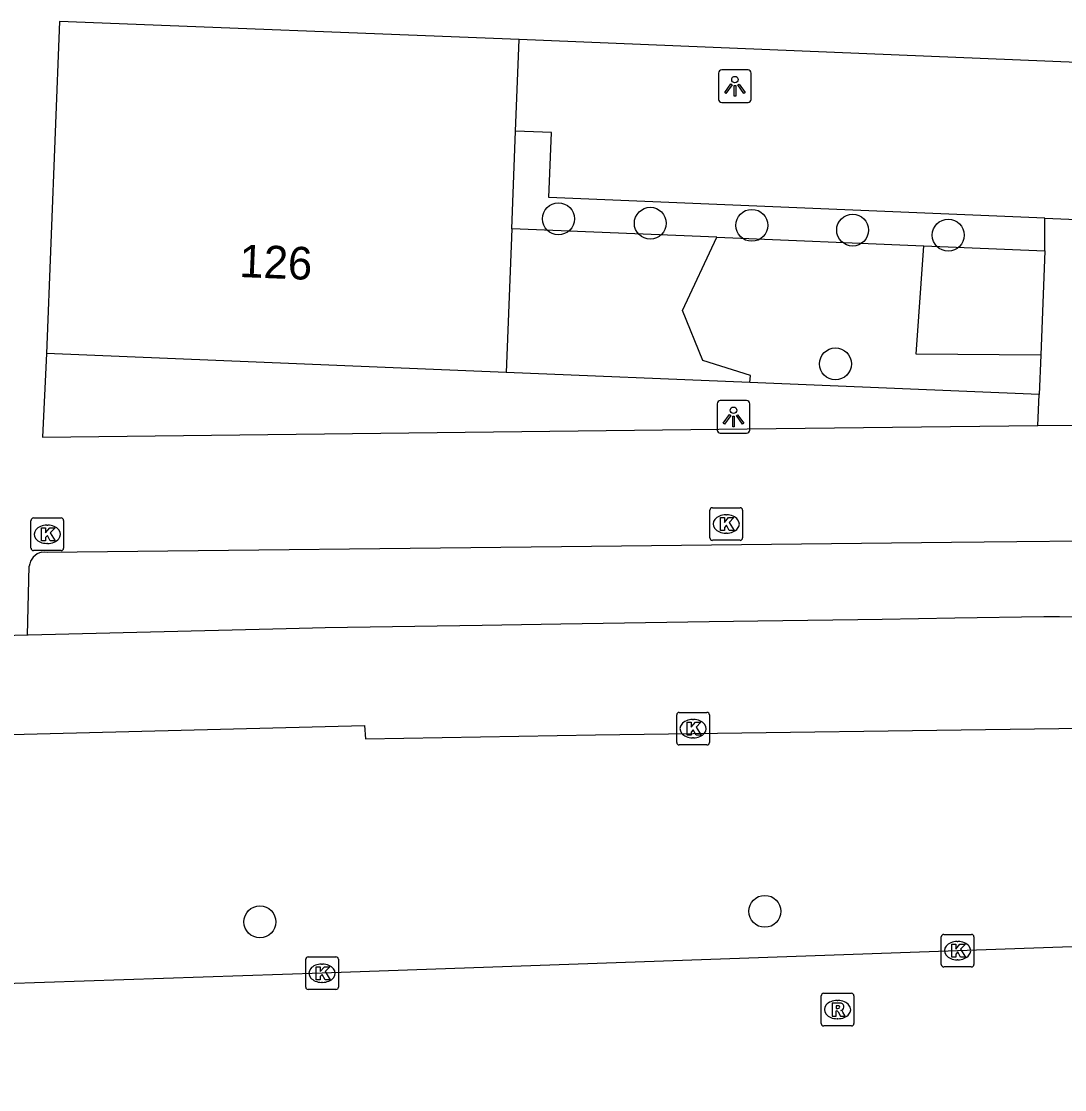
# Model space of a CAD drawing. Extents: x 160891 to 161384, y 386490 to 386907.
# Drawn here: x 161205.21 to 161237.19, y 386500.4 to 386533.16 of the extents above; entities that cross this region are included whole.
import ezdxf

# ---------------------------------------------------------------- set-up
doc = ezdxf.new("R2010")
doc.units = 0
for name, color, linetype in [('IMGEO_Boom', 7, 'Continuous'), ('IMGEO_Fietspad_gesloten', 7, 'Continuous'), ('IMGEO_Groenvoorziening', 7, 'Continuous'), ('IMGEO_Haag', 7, 'Continuous'), ('IMGEO_Kolk', 7, 'Continuous'), ('IMGEO_Lichtpunt', 7, 'Continuous'), ('IMGEO_Pand', 7, 'Continuous'), ('IMGEO_Pand_nummerreeks', 7, 'Continuous'), ('IMGEO_Parkeervlak_open', 7, 'Continuous'), ('IMGEO_Rijbaan_regionaal_gesloten', 7, 'Continuous'), ('IMGEO_Rioolput', 7, 'Continuous'), ('IMGEO_Voetgangersgebied_open', 7, 'Continuous'), ('IMGEO_Voetpad_open', 7, 'Continuous')]:
    doc.layers.add(name, color=color, linetype=linetype)

msp = doc.modelspace()

# ---------------------------------------------------------------- linework, layer by layer
at = {"layer": 'IMGEO_Boom'}
for centre in [(161221.673, 386527.103), (161224.488, 386526.967), (161227.6, 386526.903), (161230.689, 386526.757), (161233.619, 386526.601), (161230.162, 386522.654), (161227.997, 386505.867), (161212.524, 386505.543)]:
    msp.add_circle(centre, 0.489, dxfattribs=at)
at = {"layer": 'IMGEO_Fietspad_gesloten'}
for points in [[(161253.233, 386514.853), (161244.609, 386514.875), (161237.032, 386514.894), (161236.549, 386514.895), (161233.821, 386514.854), (161231.599, 386514.82), (161230.845, 386514.809), (161227.787, 386514.763), (161226.292, 386514.741), (161221.75, 386514.672), (161219.333, 386514.636), (161214.527, 386514.564), (161214.131, 386514.554), (161212.923, 386514.523), (161205.423, 386514.331), (161205.404, 386514.331)], [(161205.404, 386514.331), (161197.221, 386514.122)], [(161109.839, 386506.955), (161116.836, 386508.035), (161123.035, 386508.931), (161127.225, 386509.29), (161167.964, 386510.348), (161215.734, 386511.569), (161215.758, 386511.159), (161222.805, 386511.284), (161237.753, 386511.488), (161259.697, 386511.429), (161267.164, 386511.376), (161306.097, 386509.668), (161311.73, 386509.285), (161311.776, 386509.705), (161313.071, 386509.592)]]:
    msp.add_lwpolyline(points, dxfattribs=at)
at = {"layer": 'IMGEO_Groenvoorziening'}
for points in [[(161227.542, 386522.081), (161227.556, 386522.301), (161226.101, 386522.756), (161225.477, 386524.293), (161226.532, 386526.539)], [(161236.452, 386522.922), (161232.632, 386522.951), (161232.876, 386526.277)], [(161227.542, 386522.081), (161220.066, 386522.389)], [(161236.404, 386521.716), (161227.542, 386522.081)]]:
    msp.add_lwpolyline(points, dxfattribs=at)
at = {"layer": 'IMGEO_Haag'}
for points in [[(161226.532, 386526.539), (161220.241, 386526.799)], [(161226.532, 386526.539), (161232.876, 386526.277)], [(161232.876, 386526.277), (161236.579, 386526.123)]]:
    msp.add_lwpolyline(points, dxfattribs=at)
at = {"layer": 'IMGEO_Kolk'}
for p, q in [((161226.39, 386518.244), (161227.242, 386518.244)), ((161205.583, 386517.929), (161206.435, 386517.929)), ((161226.315, 386517.318), (161226.315, 386518.17)), ((161226.803, 386518.024), (161226.828, 386518.024)), ((161227.316, 386518.17), (161227.316, 386517.318)), ((161205.508, 386517.003), (161205.508, 386517.855)), ((161205.996, 386517.709), (161206.021, 386517.709)), ((161206.509, 386517.855), (161206.509, 386517.003)), ((161227.242, 386517.244), (161226.39, 386517.244)), ((161226.826, 386517.464), (161226.801, 386517.464)), ((161206.435, 386516.929), (161205.583, 386516.929)), ((161206.019, 386517.149), (161205.994, 386517.149)), ((161225.298, 386511.042), (161225.298, 386511.894)), ((161225.373, 386511.968), (161226.225, 386511.968)), ((161225.786, 386511.748), (161225.811, 386511.748)), ((161226.299, 386511.894), (161226.299, 386511.042)), ((161225.809, 386511.188), (161225.784, 386511.188)), ((161226.225, 386510.968), (161225.373, 386510.968)), ((161233.48, 386505.16), (161234.332, 386505.16)), ((161233.405, 386504.234), (161233.405, 386505.086)), ((161233.893, 386504.94), (161233.918, 386504.94)), ((161234.406, 386505.086), (161234.406, 386504.234)), ((161214.003, 386504.469), (161214.855, 386504.469)), ((161213.928, 386503.543), (161213.928, 386504.395)), ((161214.416, 386504.249), (161214.441, 386504.249)), ((161214.929, 386504.395), (161214.929, 386503.543)), ((161234.332, 386504.16), (161233.48, 386504.16)), ((161233.916, 386504.38), (161233.891, 386504.38)), ((161214.855, 386503.469), (161214.003, 386503.469)), ((161214.439, 386503.689), (161214.414, 386503.689))]:
    msp.add_line(p, q, dxfattribs=at)
for points in [[(161226.39, 386518.244), (161227.242, 386518.244)], [(161205.583, 386517.929), (161206.435, 386517.929)], [(161226.315, 386517.318), (161226.315, 386518.17)], [(161226.636, 386517.944), (161226.759, 386517.944), (161226.759, 386517.793), (161226.889, 386517.944), (161227.053, 386517.944), (161226.907, 386517.793), (161227.06, 386517.544), (161226.908, 386517.544), (161226.823, 386517.708), (161226.759, 386517.641), (161226.759, 386517.544), (161226.636, 386517.544), (161226.636, 386517.944)], [(161227.316, 386518.17), (161227.316, 386517.318)], [(161205.508, 386517.003), (161205.508, 386517.855)], [(161205.829, 386517.629), (161205.952, 386517.629), (161205.952, 386517.478), (161206.082, 386517.629), (161206.246, 386517.629), (161206.1, 386517.478), (161206.253, 386517.229), (161206.101, 386517.229), (161206.016, 386517.393), (161205.952, 386517.326), (161205.952, 386517.229), (161205.829, 386517.229), (161205.829, 386517.629)], [(161206.509, 386517.855), (161206.509, 386517.003)], [(161227.242, 386517.244), (161226.39, 386517.244)], [(161206.435, 386516.929), (161205.583, 386516.929)], [(161225.298, 386511.042), (161225.298, 386511.894)], [(161225.373, 386511.968), (161226.225, 386511.968)], [(161225.619, 386511.668), (161225.742, 386511.668), (161225.742, 386511.517), (161225.872, 386511.668), (161226.036, 386511.668), (161225.89, 386511.517), (161226.043, 386511.268), (161225.891, 386511.268), (161225.806, 386511.432), (161225.742, 386511.365), (161225.742, 386511.268), (161225.619, 386511.268), (161225.619, 386511.668)], [(161226.299, 386511.894), (161226.299, 386511.042)], [(161226.225, 386510.968), (161225.373, 386510.968)], [(161233.48, 386505.16), (161234.332, 386505.16)], [(161233.405, 386504.234), (161233.405, 386505.086)], [(161233.726, 386504.86), (161233.849, 386504.86), (161233.849, 386504.709), (161233.979, 386504.86), (161234.143, 386504.86), (161233.997, 386504.709), (161234.15, 386504.46), (161233.998, 386504.46), (161233.913, 386504.624), (161233.849, 386504.557), (161233.849, 386504.46), (161233.726, 386504.46), (161233.726, 386504.86)], [(161234.406, 386505.086), (161234.406, 386504.234)], [(161214.003, 386504.469), (161214.855, 386504.469)], [(161213.928, 386503.543), (161213.928, 386504.395)], [(161214.249, 386504.169), (161214.372, 386504.169), (161214.372, 386504.018), (161214.502, 386504.169), (161214.666, 386504.169), (161214.52, 386504.018), (161214.673, 386503.769), (161214.521, 386503.769), (161214.436, 386503.933), (161214.372, 386503.866), (161214.372, 386503.769), (161214.249, 386503.769), (161214.249, 386504.169)], [(161214.929, 386504.395), (161214.929, 386503.543)], [(161234.332, 386504.16), (161233.48, 386504.16)], [(161214.855, 386503.469), (161214.003, 386503.469)]]:
    msp.add_lwpolyline(points, dxfattribs=at)
for centre, start, end in [((161226.392, 386518.168), 91.552, 178.448), ((161226.392, 386518.168), 91.552, 178.448), ((161227.24, 386518.168), 1.552, 88.448), ((161227.24, 386518.168), 1.552, 88.448), ((161205.585, 386517.853), 91.552, 178.448), ((161205.585, 386517.853), 91.552, 178.448), ((161206.433, 386517.853), 1.552, 88.448), ((161206.433, 386517.853), 1.552, 88.448), ((161226.392, 386517.32), 181.552, 268.448), ((161226.392, 386517.32), 181.552, 268.448), ((161227.24, 386517.32), 271.552, 358.448), ((161227.24, 386517.32), 271.552, 358.448), ((161205.585, 386517.005), 181.552, 268.448), ((161205.585, 386517.005), 181.552, 268.448), ((161206.433, 386517.005), 271.552, 358.448), ((161206.433, 386517.005), 271.552, 358.448), ((161225.375, 386511.892), 91.552, 178.448), ((161225.375, 386511.892), 91.552, 178.448), ((161226.223, 386511.892), 1.552, 88.448), ((161226.223, 386511.892), 1.552, 88.448), ((161225.375, 386511.044), 181.552, 268.448), ((161225.375, 386511.044), 181.552, 268.448), ((161226.223, 386511.044), 271.552, 358.448), ((161226.223, 386511.044), 271.552, 358.448), ((161233.482, 386505.084), 91.552, 178.448), ((161233.482, 386505.084), 91.552, 178.448), ((161234.33, 386505.084), 1.552, 88.448), ((161234.33, 386505.084), 1.552, 88.448), ((161214.005, 386504.393), 91.552, 178.448), ((161214.005, 386504.393), 91.552, 178.448), ((161214.853, 386504.393), 1.552, 88.448), ((161214.853, 386504.393), 1.552, 88.448), ((161233.482, 386504.236), 181.552, 268.448), ((161233.482, 386504.236), 181.552, 268.448), ((161234.33, 386504.236), 271.552, 358.448), ((161234.33, 386504.236), 271.552, 358.448), ((161214.005, 386503.545), 181.552, 268.448), ((161214.005, 386503.545), 181.552, 268.448), ((161214.853, 386503.545), 271.552, 358.448), ((161214.853, 386503.545), 271.552, 358.448)]:
    msp.add_arc(centre, 0.0765, start, end, dxfattribs=at)
for centre, major_axis, ratio, start_param, end_param in [((161226.802, 386517.744), (-0.387, 0.002), 0.722429, 4.712389, 7.853982), ((161226.827, 386517.744), (-0.39, 0.002), 0.717154, 1.570796, 4.712389), ((161205.995, 386517.429), (-0.387, 0.002), 0.722429, 4.712389, 7.853982), ((161206.02, 386517.429), (-0.39, 0.002), 0.717154, 1.570796, 4.712389), ((161225.785, 386511.468), (-0.387, 0.002), 0.722429, 4.712389, 7.853982), ((161225.81, 386511.468), (-0.39, 0.002), 0.717154, 1.570796, 4.712389), ((161233.892, 386504.66), (-0.387, 0.002), 0.722429, 4.712389, 7.853982), ((161233.917, 386504.66), (-0.39, 0.002), 0.717154, 1.570796, 4.712389), ((161214.415, 386503.969), (-0.387, 0.002), 0.722429, 4.712389, 7.853982), ((161214.44, 386503.969), (-0.39, 0.002), 0.717154, 1.570796, 4.712389)]:
    msp.add_ellipse(centre, major_axis=major_axis, ratio=ratio, start_param=start_param, end_param=end_param, dxfattribs=at)
at = {"layer": 'IMGEO_Lichtpunt'}
for p, q in [((161227.485, 386531.669), (161226.677, 386531.669)), ((161227.485, 386531.669), (161226.677, 386531.669)), ((161226.583, 386531.574), (161226.583, 386530.767)), ((161226.583, 386531.574), (161226.583, 386530.767)), ((161227.579, 386530.767), (161227.579, 386531.574)), ((161227.579, 386530.767), (161227.579, 386531.574)), ((161226.677, 386530.673), (161227.485, 386530.673)), ((161226.677, 386530.673), (161227.485, 386530.673)), ((161227.441, 386521.529), (161226.633, 386521.529)), ((161227.441, 386521.529), (161226.633, 386521.529)), ((161226.539, 386521.434), (161226.539, 386520.627)), ((161226.539, 386521.434), (161226.539, 386520.627)), ((161227.535, 386520.627), (161227.535, 386521.434)), ((161227.535, 386520.627), (161227.535, 386521.434)), ((161226.633, 386520.533), (161227.441, 386520.533)), ((161226.633, 386520.533), (161227.441, 386520.533))]:
    msp.add_line(p, q, dxfattribs=at)
for points in [[(161226.957, 386531.238), (161226.996, 386531.21), (161226.808, 386530.948), (161226.77, 386530.975), (161226.957, 386531.238)], [(161227.059, 386531.19), (161227.106, 386531.19), (161227.106, 386530.868), (161227.059, 386530.868), (161227.059, 386531.19)], [(161227.169, 386531.21), (161227.207, 386531.237), (161227.394, 386530.975), (161227.355, 386530.947), (161227.169, 386531.21)], [(161226.913, 386521.098), (161226.952, 386521.07), (161226.764, 386520.808), (161226.726, 386520.835), (161226.913, 386521.098)], [(161227.015, 386521.05), (161227.062, 386521.05), (161227.062, 386520.728), (161227.015, 386520.728), (161227.015, 386521.05)], [(161227.125, 386521.07), (161227.163, 386521.097), (161227.35, 386520.835), (161227.311, 386520.807), (161227.125, 386521.07)]]:
    msp.add_lwpolyline(points, dxfattribs=at)
for centre in [(161227.082, 386531.372), (161227.038, 386521.232)]:
    msp.add_circle(centre, 0.0994, dxfattribs=at)
for centre, start, end in [((161226.677, 386531.574), 90, 180), ((161226.677, 386531.574), 90, 180), ((161227.485, 386531.574), 0, 90), ((161227.485, 386531.574), 0, 90), ((161226.677, 386530.767), 180, 270), ((161226.677, 386530.767), 180, 270), ((161227.485, 386530.767), 270, 0), ((161227.485, 386530.767), 270, 360), ((161226.633, 386521.434), 90, 180), ((161226.633, 386521.434), 90, 180), ((161227.441, 386521.434), 0, 90), ((161227.441, 386521.434), 0, 90), ((161226.633, 386520.627), 180, 270), ((161226.633, 386520.627), 180, 270), ((161227.441, 386520.627), 270, 0), ((161227.441, 386520.627), 270, 360)]:
    msp.add_arc(centre, 0.0946, start, end, dxfattribs=at)
at = {"layer": 'IMGEO_Pand'}
for points in [[(161220.471, 386532.599), (161206.385, 386533.158), (161205.979, 386522.969)], [(161220.36, 386529.791), (161220.471, 386532.599)], [(161220.241, 386526.799), (161220.36, 386529.791)], [(161220.241, 386526.799), (161220.066, 386522.389)], [(161220.066, 386522.389), (161205.979, 386522.969)]]:
    msp.add_lwpolyline(points, dxfattribs=at)
at = {"layer": 'IMGEO_Parkeervlak_open'}
for points in [[(161253.58, 386526.42), (161253.732, 386526.414), (161253.921, 386531.225), (161220.471, 386532.599)], [(161236.584, 386527.124), (161221.376, 386527.753), (161221.46, 386529.753), (161220.36, 386529.791)]]:
    msp.add_lwpolyline(points, dxfattribs=at)
at = {"layer": 'IMGEO_Rijbaan_regionaal_gesloten'}
msp.add_lwpolyline([(161323.08, 386507.769), (161322.733, 386507.751), (161292.306, 386506.7), (161273.833, 386506.048), (161254.372, 386505.373), (161233.906, 386504.66), (161214.429, 386503.969), (161194.971, 386503.319), (161175.497, 386502.675), (161154.024, 386501.918), (161133.563, 386501.204), (161132.874, 386501.189), (161113.106, 386500.507), (161110.084, 386500.399)], dxfattribs=at)
at = {"layer": 'IMGEO_Rioolput'}
for p, q in [((161229.727, 386502.427), (161229.727, 386503.279)), ((161229.802, 386503.353), (161230.654, 386503.353)), ((161230.215, 386503.133), (161230.24, 386503.133)), ((161230.728, 386503.279), (161230.728, 386502.427)), ((161230.238, 386502.573), (161230.213, 386502.573)), ((161230.654, 386502.353), (161229.802, 386502.353))]:
    msp.add_line(p, q, dxfattribs=at)
for points in [[(161229.727, 386502.427), (161229.727, 386503.279)], [(161229.802, 386503.353), (161230.654, 386503.353)], [(161230.728, 386503.279), (161230.728, 386502.427)], [(161230.316, 386503.051), (161230.064, 386503.053), (161230.064, 386502.653)], [(161230.064, 386502.653), (161230.188, 386502.653), (161230.188, 386502.815), (161230.199, 386502.815)], [(161230.242, 386502.972), (161230.188, 386502.972), (161230.188, 386502.891)], [(161230.188, 386502.891), (161230.24, 386502.891)], [(161230.246, 386502.786), (161230.317, 386502.653), (161230.457, 386502.653), (161230.392, 386502.779)], [(161230.654, 386502.353), (161229.802, 386502.353)]]:
    msp.add_lwpolyline(points, dxfattribs=at)
for centre, radius, start, end in [((161229.804, 386503.277), 0.0765, 91.552, 178.448), ((161229.804, 386503.277), 0.0765, 91.552, 178.448), ((161230.652, 386503.277), 0.0765, 1.552, 88.448), ((161230.652, 386503.277), 0.0765, 1.552, 88.448), ((161230.198, 386502.762), 0.0533, 26.0293, 88.6989), ((161230.224, 386503.08), 0.19, 274.7715, 282.9687), ((161230.248, 386502.876), 0.0964, 77.0061, 93.1865), ((161230.262, 386502.933), 0.0378, 276.6634, 79.6772), ((161230.315, 386502.941), 0.109, 350.3612, 89.416), ((161230.313, 386502.941), 0.112, 277.5842, 350.9817), ((161230.297, 386502.726), 0.108, 29.5134, 73.7905), ((161229.804, 386502.429), 0.0765, 181.552, 268.448), ((161229.804, 386502.429), 0.0765, 181.552, 268.448), ((161230.652, 386502.429), 0.0765, 271.552, 358.448), ((161230.652, 386502.429), 0.0765, 271.552, 358.448)]:
    msp.add_arc(centre, radius, start, end, dxfattribs=at)
for centre, major_axis, ratio, start_param, end_param in [((161230.214, 386502.853), (-0.387, 0.002), 0.722429, 4.712389, 7.853982), ((161230.239, 386502.853), (-0.39, 0.002), 0.717154, 1.570796, 4.712389)]:
    msp.add_ellipse(centre, major_axis=major_axis, ratio=ratio, start_param=start_param, end_param=end_param, dxfattribs=at)
at = {"layer": 'IMGEO_Voetgangersgebied_open'}
for points in [[(161205.979, 386522.969), (161205.859, 386520.404), (161227.455, 386520.659), (161236.366, 386520.764)], [(161205.844, 386516.883), (161205.917, 386516.886), (161206.016, 386516.884), (161206.921, 386516.896), (161221.767, 386517.056), (161233.722, 386517.186), (161239.735, 386517.251), (161252.478, 386517.39), (161252.863, 386517.39)], [(161205.404, 386514.331), (161205.457, 386516.449)]]:
    msp.add_lwpolyline(points, dxfattribs=at)
msp.add_arc((161205.938, 386516.409), 0.483, 101.2631, 175.2898, dxfattribs=at)
at = {"layer": 'IMGEO_Voetpad_open'}
for points in [[(161236.579, 386526.123), (161236.584, 386527.124)], [(161236.584, 386527.124), (161253.58, 386526.42)], [(161236.579, 386526.123), (161236.452, 386522.922)], [(161236.452, 386522.922), (161236.404, 386521.716)], [(161236.366, 386520.764), (161237.489, 386520.777), (161238.58, 386520.79), (161238.627, 386521.923)], [(161236.366, 386520.764), (161236.404, 386521.716)]]:
    msp.add_lwpolyline(points, dxfattribs=at)

# ---------------------------------------------------------------- texts
at = {"layer": 'IMGEO_Pand_nummerreeks'}
msp.add_text('126', height=1, rotation=357.6671, dxfattribs=at).set_placement((161211.878, 386525.32))

doc.saveas('drawing.dxf')
